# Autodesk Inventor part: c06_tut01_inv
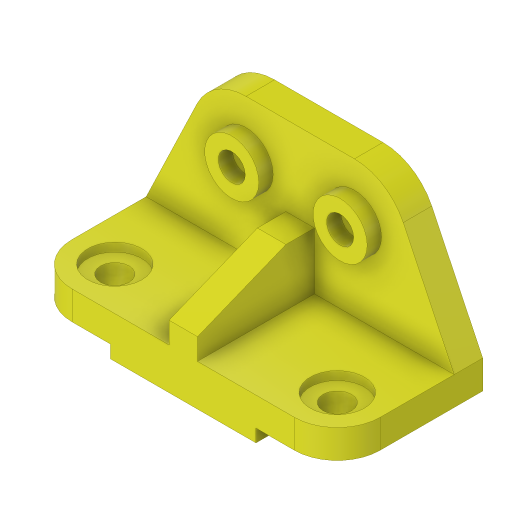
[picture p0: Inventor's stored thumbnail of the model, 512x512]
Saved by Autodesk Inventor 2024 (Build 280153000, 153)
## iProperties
Created: 2015-03
Part Number: c06_tut01_inv
Material: Generic
Document SubType Name: Modeling
Designer: Sandeep
Density: 1 g/cm^3
Appearance: Yellow
Author: Sandeep
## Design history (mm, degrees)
sketch "Sketch1"
  geometry: L1 (51, 0)-(51, 9); L2 (51, 9)-(108, 9); L3 (108, 9)-(108, 29); L4 (108, 29)-(-108, 29); L5 (-108, 29)-(-108, 9); L6 (-108, 9)-(-51, 9); L7 (-51, 9)-(-51, 0); L8 (-51, 0)-(51, 0); L9 (0, 96.725)-(0, -45.323); 1 further point
  constraints: 18 end point, 6 perpendicular, 3 point on line, 2 vertical, 1 midpoint, 2 other
  dimensions: "d1" = 20 distance of L2.end L3.end; "d2" = 57 distance between parallel lines of L5 L7; "d3" = 102 distance between parallel lines of L7 L1; "d66" = 9 distance between parallel lines of L2 L8
extrude "Extrusion1" new body sketch "Sketch1" distance "d4" = 102; taper "d5" = 0 deg
sketch "Sketch2"
  geometry: L1 (-108, -29)-(108, -29) reference; L2 (108, -29)-(72.256, -103.447); L3 (38, -125)-(-38, -125); L4 (-72.256, -103.447)-(-108, -29); L5 (0, -125)-(0, -29); L6 (51, 0)-(-51, 0) reference; A1 r 38 centre (38, -87) between (38, -125) and (72.256, -103.447); A2 r 38 centre (-38, -87) between (-72.256, -103.447) and (-38, -125); 2 further points
  constraints: 8 end point, 4 point on circle, 4 tangent, 3 midpoint, 2 centre point, 1 parallel, 1 point on line, 1 vertical, 2 other
  dimensions: "d6" = 96 distance between parallel lines of L1 L3; "d7" = 38 radius of A2; "d8" = 76 distance of L3.start L3.end
extrude "Extrusion2" join sketch "Sketch2" distance "d9" = 20; taper "d10" = 0 deg
sketch "Sketch3"
  geometry: L1 (0, 198.489)-(0, -42.784); L2 (38, 125)-(-38, 125) reference; C1 r 19 at (-38, 87); C2 r 9.5 at (-38, 87); C3 r 9.5 at (38, 87); C4 r 19 at (38, 87); 2 further points
  constraints: 4 centre point, 2 coincident, 2 end point, 2 equal radius, 1 midpoint, 1 point on line, 1 vertical, 2 other
  dimensions: "d11" = 38 diameter of C1; "d12" = 19 diameter of C2; "d13" = 76 distance of C3.centre C1.centre; "d14" = 38 distance from line of C1.centre L2
extrude "Extrusion3" join sketch "Sketch3" distance "d15" = 10; taper "d16" = 0 deg
fillet "Fillet1" dims "d17" = 30
hole "Hole3" diameter "d38" = 20; stored, may be unused: countersink angle "d42" = 90 deg, drill point angle "d44" = 118 deg; dims "d39" = 6, "d40" = 38, "d41" = 6, "d43" = 8, "d64" = 10, "d65" = 10
hole "Hole4" diameter "d47" = 20; stored, may be unused: countersink angle "d51" = 90 deg, drill point angle "d53" = 118 deg; dims "d45" = 10, "d46" = 10, "d48" = 6, "d49" = 38, "d50" = 6, "d52" = 8
workplane "Work Plane1"
sketch "Sketch4"
  geometry: L1 (-40, 0.112)-(-40, -20); L2 (-40, -20)-(-15, -82); L3 (20, -82)-(0, -82) reference; L4 (-15, -82)-(0, -82); L5 (0, -52)-(0, 0) reference; L6 (-96, 0)-(-74.447, 0) reference; 1 further point
  constraints: 6 end point, 1 collinear, 1 vertical
  dimensions: "d55" = 40 distance between parallel lines of L1 L5; "d56" = 20 distance from line of L6 L1.end; "d57" = 15 distance of L2.end L3.end
feature "Rib1" sketch "Sketch4" dims "d58" = 1, "d59" = 20, "d60" = 0, "d61" = 0, "d62" = 1, "d63" = 1
body "Solid1"
other parameters: "d54" = -108
